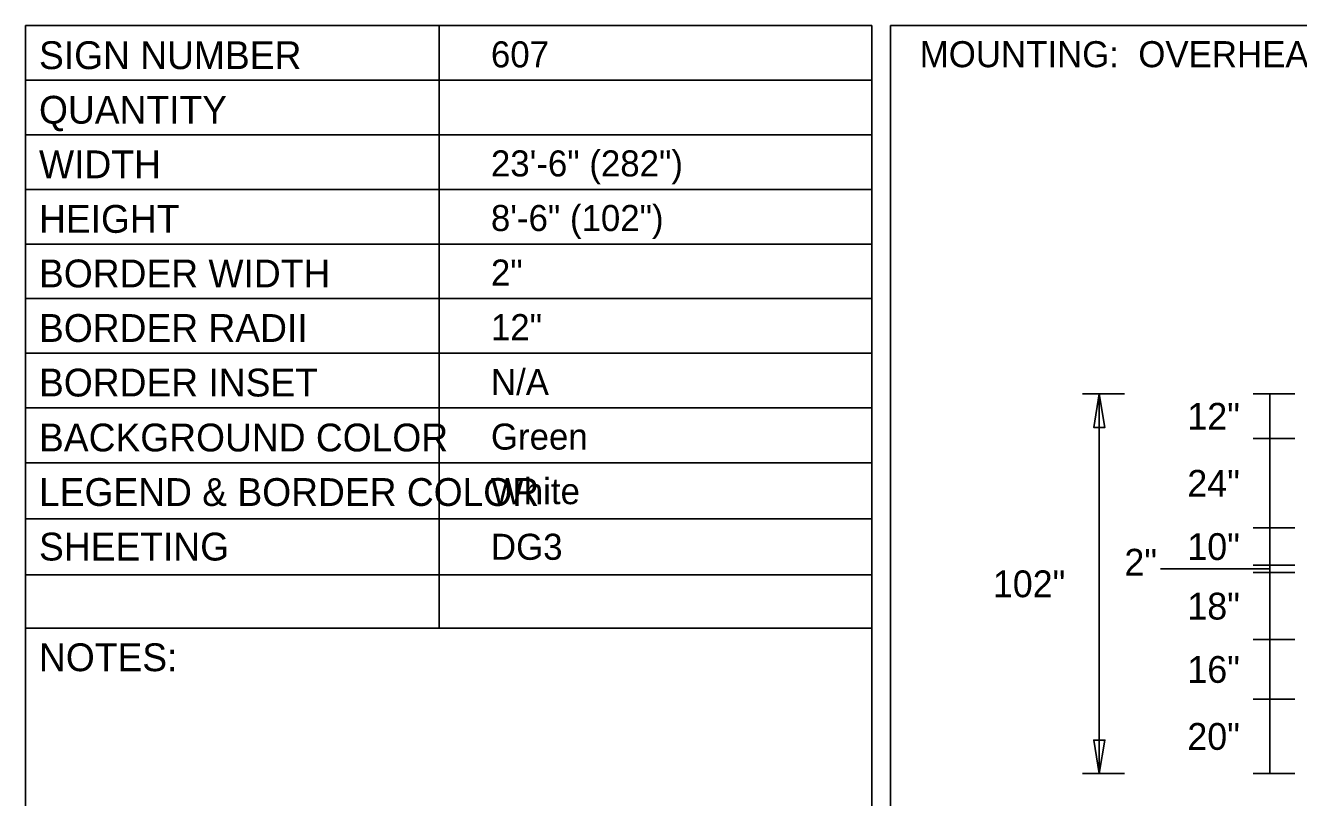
# Model space of a CAD drawing. Extents: x 10268259 to 10268554, y 2141099 to 2141249.
# Drawn here: x 10268318.48 to 10268352.7, y 2141134.79 to 2141155.53 of the extents above; entities that cross this region are included whole.
import ezdxf

# ---------------------------------------------------------------- set-up
doc = ezdxf.new("R2010")
doc.units = 0
for name, color, linetype in [('60', 7, 'Continuous'), ('62', 7, 'Continuous'), ('GSDims', 7, 'Continuous'), ('TextMisc', 7, 'Continuous')]:
    doc.layers.add(name, color=color, linetype=linetype)

msp = doc.modelspace()

# ---------------------------------------------------------------- linework, layer by layer
at = {"layer": '60'}
for p, q in [((10268318.48, 2141155.528), (10268318.48, 2141125.528)), ((10268318.48, 2141155.528), (10268341.23, 2141155.528)), ((10268329.598, 2141155.525), (10268329.598, 2141139.341)), ((10268341.23, 2141155.528), (10268341.23, 2141125.528)), ((10268341.73, 2141155.528), (10268341.73, 2141125.528)), ((10268341.73, 2141155.528), (10268393.98, 2141155.528)), ((10268318.48, 2141154.063), (10268341.23, 2141154.063)), ((10268318.48, 2141152.587), (10268341.23, 2141152.587)), ((10268318.48, 2141151.121), (10268341.23, 2141151.121)), ((10268318.48, 2141149.655), (10268341.23, 2141149.655)), ((10268318.48, 2141148.19), (10268341.23, 2141148.19)), ((10268318.48, 2141146.724), (10268341.23, 2141146.724)), ((10268318.48, 2141145.258), (10268341.23, 2141145.258)), ((10268318.48, 2141143.782), (10268341.23, 2141143.782)), ((10268318.48, 2141142.278), (10268341.23, 2141142.278)), ((10268318.48, 2141140.773), (10268341.23, 2141140.773)), ((10268318.478, 2141139.341), (10268341.229, 2141139.341))]:
    msp.add_line(p, q, dxfattribs=at)
at = {"layer": 'GSDims'}
for p, q in [((10268348.018, 2141145.628), (10268346.893, 2141145.628)), ((10268347.343, 2141135.428), (10268347.343, 2141145.628)), ((10268352.6, 2141145.628), (10268351.475, 2141145.628)), ((10268351.925, 2141135.428), (10268351.925, 2141145.628)), ((10268351.475, 2141144.428), (10268352.6, 2141144.428)), ((10268351.475, 2141142.028), (10268352.6, 2141142.028)), ((10268348.986, 2141140.928), (10268351.925, 2141140.928)), ((10268351.475, 2141141.028), (10268352.6, 2141141.028)), ((10268351.475, 2141140.828), (10268352.6, 2141140.828)), ((10268351.475, 2141139.028), (10268352.6, 2141139.028)), ((10268351.475, 2141137.428), (10268352.6, 2141137.428)), ((10268348.018, 2141135.428), (10268346.893, 2141135.428)), ((10268352.6, 2141135.428), (10268351.475, 2141135.428))]:
    msp.add_line(p, q, dxfattribs=at)
for points in [[(10268347.343, 2141145.628), (10268347.493, 2141144.728), (10268347.193, 2141144.728)], [(10268347.343, 2141135.428), (10268347.493, 2141136.328), (10268347.193, 2141136.328)]]:
    msp.add_lwpolyline(points, close=True, dxfattribs=at)

# ---------------------------------------------------------------- texts
at = {"layer": '62'}
for s, p in [('607', (10268330.99, 2141154.403)), ('MOUNTING:  OVERHEAD CANTILEVER (OC-X)', (10268342.516, 2141154.407)), ('23\'-6" (282")', (10268330.99, 2141151.472)), ('8\'-6" (102")', (10268330.99, 2141150.006)), ('2"', (10268330.99, 2141148.54)), ('12"', (10268330.99, 2141147.074)), ('N/A', (10268330.99, 2141145.599)), ('Green', (10268330.99, 2141144.133)), ('White', (10268330.99, 2141142.667)), ('DG3', (10268330.99, 2141141.173))]:
    msp.add_text(s, height=0.7, dxfattribs=at).set_placement(p)
at = {"layer": 'GSDims'}
for s, p in [('12"', (10268349.71, 2141144.668)), ('24"', (10268349.71, 2141142.868)), ('10"', (10268349.71, 2141141.168)), ('2"', (10268348.018, 2141140.748)), ('102"', (10268344.482, 2141140.168)), ('18"', (10268349.71, 2141139.568)), ('16"', (10268349.71, 2141137.868)), ('20"', (10268349.71, 2141136.068))]:
    msp.add_text(s, height=0.72, dxfattribs=at).set_placement(p)
at = {"layer": 'TextMisc'}
for s, height, p in [('SIGN NUMBER', 0.74756, (10268318.842, 2141154.356)), ('QUANTITY', 0.7476, (10268318.842, 2141152.89)), ('WIDTH', 0.7476, (10268318.842, 2141151.424)), ('HEIGHT', 0.7476, (10268318.842, 2141149.958)), ('BORDER WIDTH', 0.74756, (10268318.842, 2141148.493)), ('BORDER RADII', 0.74756, (10268318.842, 2141147.027)), ('BORDER INSET', 0.74756, (10268318.842, 2141145.561)), ('BACKGROUND COLOR', 0.74756, (10268318.842, 2141144.085)), ('LEGEND & BORDER COLOR', 0.74756, (10268318.842, 2141142.62)), ('SHEETING', 0.7476, (10268318.842, 2141141.154)), ('NOTES:', 0.7476, (10268318.841, 2141138.181))]:
    msp.add_text(s, height=height, dxfattribs=at).set_placement(p)

doc.saveas('drawing.dxf')
